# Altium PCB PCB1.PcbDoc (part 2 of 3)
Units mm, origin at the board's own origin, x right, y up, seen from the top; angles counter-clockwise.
Board outline 131.32 x 71.5 mm, 4 copper layers (Top Layer, Layer 1, Layer 2, Bottom Layer), stack 0.603 mm thick; 122 components, 132 nets, 671 pads, 444 vias.
Unrouted connection lines stored in the file: 1.
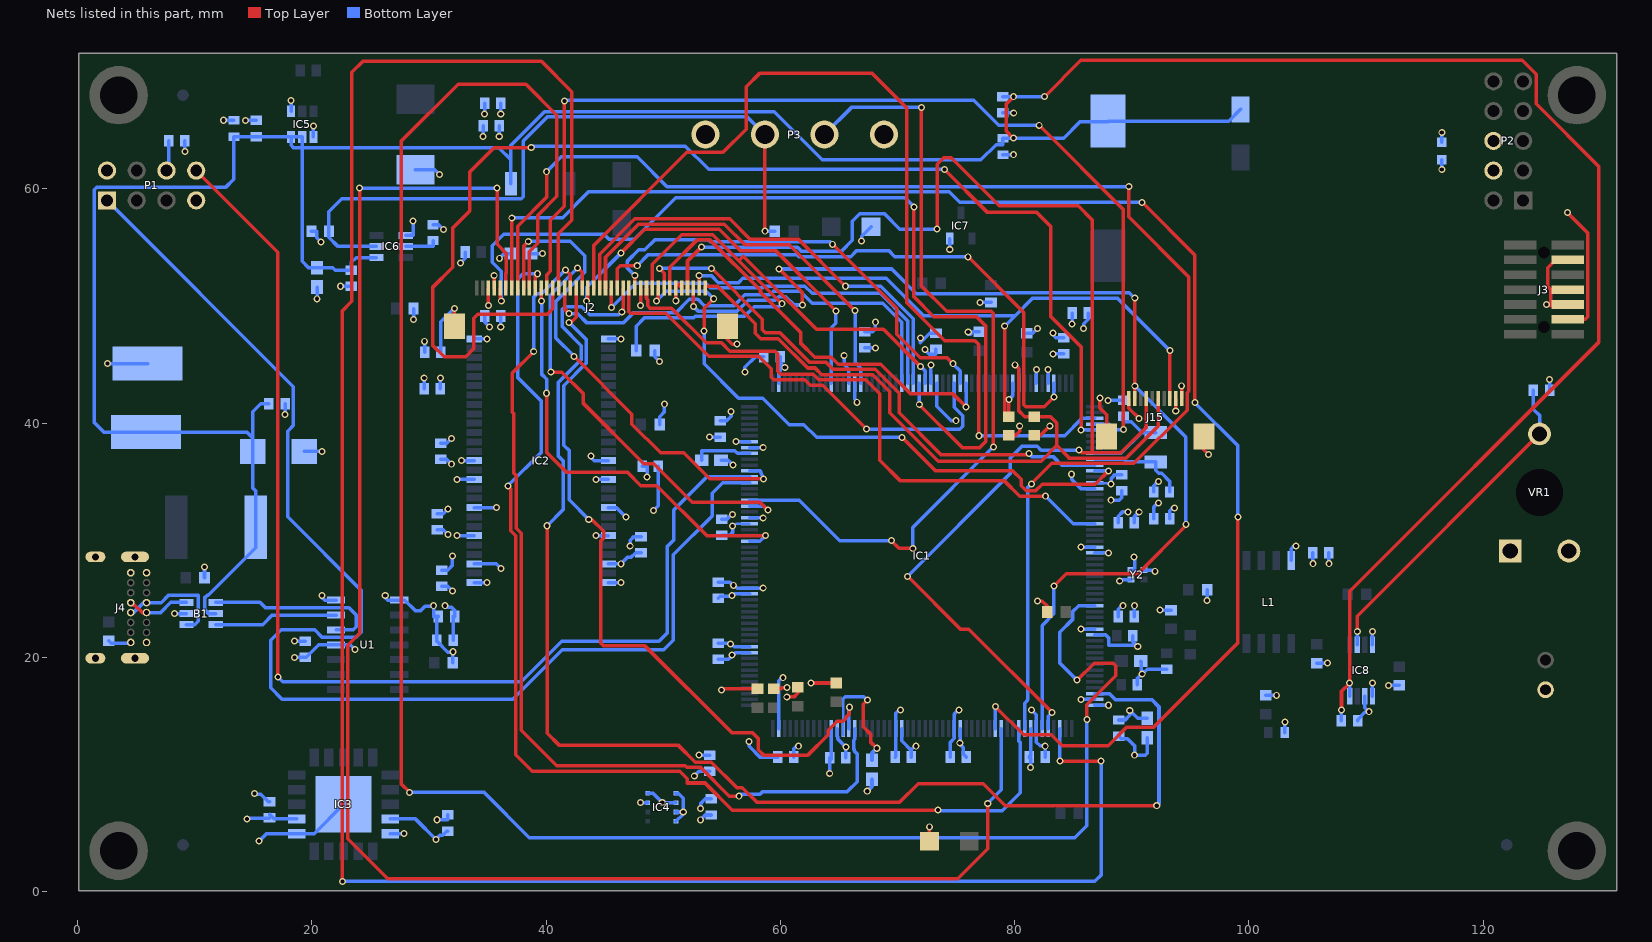
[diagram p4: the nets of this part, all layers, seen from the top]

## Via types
v1: diameter 0.6, hole 0.35, Top Layer to Bottom Layer, 444 vias

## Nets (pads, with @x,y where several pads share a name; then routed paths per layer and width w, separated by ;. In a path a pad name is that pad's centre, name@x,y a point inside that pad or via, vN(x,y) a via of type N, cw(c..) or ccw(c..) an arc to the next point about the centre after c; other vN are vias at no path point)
3V3: C3.1 C4.2 C9.2 C10.2 C11.2 C12.2 C13.2 C14.2 C15.2 C16.2 C17.2 C18.2 C19.2 C20.2 C21.2 C24.2 C25.2 C26.2 C27.2 C28.2 C29.2 C30.2 C33.2 C34.2 C35.1 C36.2 C37.2 C46.2 C47.2 C49.2 C50.2 C51.2 C52.2 C55.2 C56.2 C57.1 C58.2 C59.1 C60.2 C61.2 C62.2 Ferrite.1 IC1.15 IC1.26 IC1.39 IC1.52 IC1.59 IC1.73 IC1.83 IC1.94 IC1.103 IC1.115 IC1.124 IC1.137 IC1.150 IC1.158 IC1.171 IC1.185 IC1.204 IC2.1 IC2.3 IC2.9 IC2.14 IC2.27 IC2.43 IC2.49 IC3.7 IC3.19 IC4.2 IC4.5 IC4.6 IC4.8 IC5.1 IC8.5 J2.4 J3.3 J15.9 L1.8 L3.2 LED1.1 P1.2 P1.6 P2.4 P3.4 R2.1 R3.2 R4.1 R6.1 R9.2 R10.2 R11.1 R12.1 R13.1 R14.1 R17.2 R18.2 R24.1 U1.1 U1.11 VR1.A1 Y2.1 Y2.4 | length 169.9
  Top Layer w0.3: J2.4@35.567,51.529 v1(35.567,52.606) ; v1(54.954,17.221) 55.043,17.31 R9.2@58.039,17.31 ; R11.1@59.436,17.31 60.02,17.31 60.135,17.424 v1(60.554,17.424) ; v1(60.541,16.624) 61.163,16.624 61.468,16.929 R10.2@61.468,17.437 ; v1(62.624,17.818) R12.1@64.77,17.818 ; LED1.1@72.722,4.318 v1(72.722,5.545) ; R18.2@79.502,38.951 80.061,38.951 80.429,39.319 v1(80.429,39.764) ; R17.2@81.661,38.951 82.182,38.951 v1(82.994,39.764) ; v1(81.953,24.803) 82.36,24.803 82.766,24.397 R4.1@82.766,23.876 ; v1(93.75,41.037) J15.9@93.75,42.114 ; v1(127.178,57.988) 128.93,56.236 128.93,49.098 128.694,48.862 J3.3@127.221,48.862
  Bottom Layer w0.3: P1.6@7.366,61.341 P1.6@7.587,61.562 7.786,61.761 C57.1@7.786,64.102 ; v1(14.478,6.223) 14.514,6.259 16.347,6.259 C4.2@16.383,6.295 ; C4.2@16.383,6.602 16.775,6.21 IC3.7@18.7,6.21 ; v1(18.509,20.011) C61.2@19.431,20.011 19.521,20.011 20.592,21.082 U1.11@22.065,21.082 23.267,21.082 v1(23.673,20.676) ; IC5.1@20.127,64.433 v1(20.127,65.36) ; v1(26.263,25.298) 26.263,25.121 26.492,24.892 U1.1@27.465,24.892 27.94,24.892 28.829,24.003 29.304,24.003 29.661,24.36 30.342,24.36 v1(30.4,24.417) 30.4,23.495 C62.2@30.679,23.495 ; IC3.19@26.7,6.21 28.842,6.21 v1(30.607,4.445) 30.607,4.5 30.933,4.826 31.156,4.826 31.5,5.17 C37.2@31.59,5.17 ; L3.2@28.829,61.643 30.475,61.643 v1(30.881,61.237) ; C55.2@29.591,42.926 v1(29.591,43.848) ; C30.2@29.63,46.068 v1(29.63,46.99) ; C25.2@30.701,32.28 31.217,32.28 v1(31.623,32.686) ; C62.2@30.806,23.495 C62.2@30.679,23.495 ; C27.2@30.988,36.902 31.504,36.902 v1(31.91,36.496) ; C28.2@31.082,27.454 31.598,27.454 32.004,27.86 v1(32.004,28.673) ; R24.1@32.042,19.558 v1(32.042,20.485) 32.004,20.447 31.605,20.447 30.679,21.373 C60.2@30.679,21.463 C62.2@30.679,23.495 ; v1(32.788,36.797) IC2.14@33.863,36.797 ; IC2.1@33.863,26.397 v1(34.937,26.397) ; IC2.3@33.863,27.997 35.75,27.997 v1(36.157,27.591) ; IC2.9@33.863,32.797 v1(35.75,32.797) ; IC2.27@33.863,47.197 v1(34.937,47.197) ; v1(34.616,64.483) C47.2@34.616,65.405 ; v1(34.743,66.388) C46.2@34.743,67.31 ; v1(36.013,54.077) 36.419,54.483 C35.1@37.019,54.483 ; v1(36.123,48.227) C34.2@36.123,49.149 ; v1(44.244,30.397) IC2.49@45.319,30.397 ; v1(44.244,35.197) IC2.43@45.319,35.197 ; v1(47.178,29.511) 47.178,29.997 47.505,30.324 C29.2@48.1,30.324 ; v1(48.051,7.606) IC4.2@48.678,7.606 ; C26.2@48.205,36.322 48.611,36.322 v1(48.611,35.4) ; IC4.5@51.078,6.006 51.648,6.576 51.648,6.749 v1(51.705,6.806) ; IC4.6@51.078,6.806 v1(51.705,6.806) ; IC4.8@51.078,8.406 51.128,8.356 51.334,8.356 51.705,7.985 v1(51.705,6.806) ; v1(53.053,11.667) C33.2@53.975,11.667 ; v1(53.18,7.116) 53.18,7.523 53.586,7.929 C36.2@54.102,7.929 ; C49.2@54.704,21.231 54.741,21.194 55.687,21.194 v1(55.724,21.156) 55.806,21.156 56.043,20.919 IC1.115@57.365,20.919 ; C20.2@54.704,25.058 54.862,25.216 55.823,25.216 v1(55.88,25.273) 55.961,25.273 56.107,25.419 IC1.124@57.365,25.419 ; C18.2@54.864,40.187 55.38,40.187 55.786,40.593 v1(55.786,41) ; C19.2@54.991,31.805 55.441,31.805 55.847,32.211 v1(55.913,32.211) ; v1(56.2,38.419) IC1.150@57.365,38.419 ; v1(57.324,12.828) 57.324,12.422 58.246,11.5 C50.2@59.762,11.5 ; IC1.137@57.365,31.919 v1(58.53,31.919) ; IC1.103@59.853,13.931 59.853,18.009 60.114,18.269 v1(60.216,18.269) ; IC1.158@59.853,43.407 59.853,44.374 59.966,44.487 59.966,45.171 ; C16.2@59.966,45.687 59.966,45.171 ; v1(60.372,44.765) 59.966,45.171 ; v1(64.207,10.102) C51.2@64.207,11.43 ; C51.2@64.353,11.303 IC1.94@64.353,13.931 ; IC1.171@66.353,43.407 66.353,42.059 66.548,41.864 v1(66.548,41.783) ; C15.2@67.183,46.427 v1(68.105,46.427) ; C52.2@69.795,11.5 69.853,11.558 IC1.83@69.853,13.931 69.853,15.251 70.104,15.502 v1(70.259,15.502) ; v1(72.357,46.3) 72.357,46.253 72.717,45.894 73.279,45.894 C14.2@73.279,46.3 ; IC1.185@73.353,43.407 73.353,41.43 74.572,40.21 v1(74.979,40.21) ; C58.2@74.494,11.5 74.494,12.744 74.853,13.103 IC1.73@74.853,13.931 74.853,15.171 75.184,15.502 v1(75.259,15.502) ; R2.1@81.026,47.663 81.547,47.663 v1(81.953,48.069) ; v1(81.447,15.502) 81.853,15.096 IC1.59@81.853,13.931 81.853,12.762 82.169,12.446 82.581,12.446 v1(82.605,12.422) C17.2@82.605,11.5 ; IC1.204@82.853,43.407 v1(82.853,44.572) ; v1(83.279,45.919) C13.2@84.201,45.919 ; v1(84.864,35.638) 84.864,35.192 85.637,34.419 IC1.15@86.841,34.419 ; v1(85.676,22.419) IC1.39@86.841,22.419 ; v1(85.882,48.075) 85.882,48.481 86.288,48.887 C56.2@86.288,49.403 ; IC1.52@86.841,15.919 v1(88.006,15.919) ; IC1.26@86.841,28.919 v1(88.006,28.919) ; v1(88.232,33.422) 88.921,33.422 89.154,33.655 C11.2@89.154,34.235 ; C10.2@88.845,23.495 88.845,24.105 89.157,24.417 v1(89.251,24.417) ; C24.2@88.845,31.496 88.845,32.058 89.205,32.418 v1(89.658,32.418) ; C9.2@88.9,13.28 89.11,13.07 89.626,13.07 90.228,12.467 v1(90.228,11.654) 91.137,11.654 91.313,11.83 C3.1@91.313,13.143 ; v1(88.966,26.543) 89.074,26.651 Y2.4@89.92,26.651 ; Y2.1@89.92,27.451 90.264,27.451 90.264,28.495 v1(90.185,28.575) ; C12.2@91.86,31.844 91.86,32.842 92.19,33.172 v1(92.266,33.172) ; v1(92.418,24.041) Ferrite.1@93.345,24.041 ; v1(96.431,24.854) R3.2@96.431,25.781 ; R6.1@101.44,16.769 v1(102.367,16.769) ; L1.8@103.599,28.282 103.599,29.273 103.835,29.509 v1(104.005,29.509) ; R13.1@105.791,19.52 v1(106.718,19.52) ; v1(106.829,28.001) C21.2@106.829,28.923 ; IC8.5@110.543,16.69 v1(110.543,17.817) ; v1(111.911,17.615) R14.1@112.838,17.615 ; v1(116.459,61.669) C59.1@116.459,62.496
+5: +5.1 B1.5 C32.1 C39.2 C42.2 C44.2 C45.2 C48.2 C53.2 C54.2 D1.1 D5.1 F1.2 IC5.2 IC5.3 IC6.1 IC8.8 L2.1 LS1.1 | length 304.9
  Top Layer w0.3: v1(79.891,64.337) 79.299,64.929 79.299,67.259 v1(79.908,67.869) ; v1(82.554,67.873) 85.649,70.968 123.342,70.968 124.511,69.799 124.511,67.259 129.845,61.925 129.845,46.888 108.593,25.637 v1(108.593,17.805) 107.899,17.112 v1(107.899,15.519)
  Bottom Layer w0.3: B1.5@11.791,23.749 11.176,23.749 10.871,24.054 10.871,25.121 11.074,25.324 11.157,25.324 15.196,29.362 F1.2@15.196,31.115 15.196,34.214 14.945,34.465 D1.1@14.945,37.592 14.945,38.725 ; C42.2@16.328,41.656 15.631,41.656 14.945,40.97 14.945,38.725 ; IC6.1@25.514,54.135 23.774,54.135 23.368,53.729 C54.2@23.368,53.069 22.002,53.069 21.793,53.278 C32.1@20.447,53.278 19.71,53.278 19.177,53.811 19.177,63.525 ; L2.1@36.997,60.452 36.997,62.484 ; C45.2@78.994,67.873 v1@79.904,67.873 ; v1(79.908,67.869) v1@79.904,67.873 ; v1(82.554,67.873) v1@79.904,67.873 ; D5.1@99.281,66.787 98.282,65.788 LS1.1@87.978,65.788 87.978,65.735 85.574,65.735 84.176,64.337 v1(79.891,64.337) C44.2@78.994,64.337 78.994,63.779 78.41,63.779 77.114,62.484 63.576,62.484 59.467,66.593 39.861,66.593 36.997,63.729 36.997,62.484 ; C39.2@107.895,14.605 107.895,15.515 v1(107.899,15.519) ; IC8.8@108.593,16.69 v1(108.593,17.805) ; 14.945,38.725 14.427,39.243 +5.1@5.842,39.243 2.235,39.243 1.422,40.056 1.422,59.919 1.626,60.122 12.624,60.122 13.335,60.833 C53.2@13.335,64.441 14.275,64.441 14.295,64.461 C48.2@15.24,64.461 16.713,64.461 16.741,64.433 IC5.3@18.227,64.433 ; IC5.3@18.227,64.433 18.227,63.729 18.43,63.525 19.177,63.525 ; IC5.3@18.227,64.433 IC5.2@19.177,64.433 19.177,63.525 ; 19.177,63.525 35.956,63.525 36.997,62.484
D+: B1.1 J4.A6 J4.B6 | length 9.7
  Bottom Layer w0.3: J4.B6@4.534,23.832 4.775,23.832 5.625,24.682 J4.A6@5.884,24.682 7.137,24.682 7.754,25.299 10.287,25.299 10.287,23.089 9.997,22.799 B1.1@9.291,22.799
D-: B1.3 J4.A7 J4.B7 | length 5.5
  Top Layer w0.3: J4.B7@4.534,24.682 4.756,24.46 4.877,24.46 5.505,23.832 J4.A7@5.884,23.832
  Bottom Layer w0.3: J4.A7@5.884,23.832 7.087,23.832 7.954,24.699 B1.3@9.291,24.699
ESP_RX: IC1.143 P1.1 | length 113.2
  Bottom Layer w0.3: P1.1@2.507,59.022 18.415,43.114 18.415,39.802 17.932,39.319 17.932,32.004 24.232,25.705 24.232,22.2 23.774,21.742 20.853,21.742 20.244,22.352 17.374,22.352 16.485,21.463 16.485,17.399 17.45,16.434 37.16,16.434 41.377,20.65 50.038,20.65 50.851,21.463 50.851,28.753 54.178,32.08 54.178,34.03 55.067,34.919 IC1.143@57.365,34.919
ESP_TX: IC1.144 P1.8 | length 99.6
  Top Layer w0.3: P1.8@10.127,61.562 17.094,54.595 v1(17.094,18.339)
  Bottom Layer w0.3: v1(17.094,18.339) 17.501,17.932 37.871,17.932 41.326,21.387 49.632,21.387 50.317,22.073 50.317,29.447 50.896,30.025 50.896,32.582 53.732,35.419 IC1.144@57.365,35.419
GND: B1.2 C1.1 C2.1 C3.2 C4.1 C5.2 C6.2 C7.2 C8.1 C9.1 C10.1 C11.1 C12.1 C13.1 C14.1 C15.1 C16.1 C17.1 C18.1 C19.1 C20.1 C21.1 C22.1 C23.1 C24.1 C25.1 C26.1 C27.1 C28.1 C29.1 C30.1 C31.1 C32.2 C33.1 C34.1 C35.2 C36.1 C37.1 C38.1 C39.1 C40.1 C41.1 C42.1 C44.1 C45.1 C46.1 C47.1 C48.1 C49.1 C50.1 C51.1 C52.1 C53.1 C54.1 C55.1 C56.1 C57.2 C58.1 C59.2 C60.1 C61.1 C62.1 D1.2 GND.1 IC1.14 IC1.25 IC1.40 IC1.51 IC1.60 IC1.72 IC1.82 IC1.93 IC1.114 IC1.125 IC1.136 IC1.149 IC1.170 IC1.184 IC1.202 IC2.6 IC2.12 IC2.28 IC2.41 IC2.46 IC2.52 IC2.54 IC3.6 IC3.20 IC3.21 IC4.1 IC4.7 IC5.4 IC6.4 IC7.2 IC8.4 IC8.6 J2.3 J2.29 J2.35 J2.36 J2.41 J2.42 J3.5 J3.7 J3.11 J4.A1 J4.A12 J4.B1 J4.B12 J4.S1 J4.S2 J4.S3 J4.S4 J15.1 J15.10 J15.11 J15.12 LED2.2 P1.7 P2.6 P3.1 Q1.1 R1.2 R7.1 R8.1 R16.2 R21.1 R22.1 R23.1 R26.1 U1.14 VR1.E1 Y2.2 | length 183.7
  Top Layer w0.3: J2.41@32.167,48.279 v1(32.167,49.806) ; v1(35.067,50.046) J2.3@35.067,51.529 ; v1(48.067,50.046) J2.29@48.067,51.529 ; v1(51.067,50.452) 51.067,51.864 51.317,51.864 ; J2.35@51.097,51.864 51.567,51.864 J2.36@51.567,51.529 51.317,51.779 ; J2.42@55.467,48.279 55.467,47.158 55.873,46.752 v1(56.28,46.752) ; v1(87.274,42.142) 87.274,41.297 87.85,40.721 J15.11@87.85,38.864 ; J15.1@89.75,42.114 89.75,41.28 v1(90.627,40.403) ; J15.10@94.25,42.114 v1(94.25,43.191) ; J15.12@96.15,38.864 96.15,37.743 v1(96.556,37.337) ; v1(125.399,50.132) 125.456,50.075 125.668,50.075 125.705,50.038 125.781,50.038 125.781,51.402 ; 125.781,50.132 J3.5@127.221,50.132 ; J3.7@127.221,51.402 125.781,51.402 ; J3.11@127.221,53.942 126.187,53.942 125.501,53.256 125.501,51.681 125.781,51.402
  Bottom Layer w0.2: v1(55.913,31.238) 55.988,31.313 56.096,31.313 56.202,31.419 IC1.136@57.365,31.419 ; IC1.14@86.841,34.919 86.891,34.869 88.165,34.869 v1(88.232,34.802)
  Bottom Layer w0.3: v1(2.542,45.085) GND.1@5.969,45.085 ; R22.1@2.667,21.425 2.877,21.215 4.467,21.215 J4.B1@4.534,21.282 ; v1(8.264,23.749) B1.2@9.291,23.749 ; v1(9.166,63.18) C57.2@9.166,64.102 ; R23.1@10.833,26.797 v1(10.833,27.724) ; v1(12.438,65.861) C53.1@13.335,65.861 ; v1(14.318,65.841) C48.1@15.24,65.841 ; v1(15.113,8.382) 15.17,8.325 15.643,8.325 16.293,7.675 C4.1@16.383,7.675 ; v1(15.494,4.318) 15.494,4.329 16.125,4.96 IC3.6@18.7,4.96 20.2,4.96 IC3.21@22.7,7.46 ; v1(17.708,40.734) C42.1@17.708,41.656 ; IC5.4@18.227,66.631 v1(18.227,67.558) ; v1(18.509,21.391) C61.1@19.431,21.391 ; D1.2@19.345,37.592 v1(20.872,37.592) ; R16.2@19.951,56.388 20.401,56.388 20.401,55.824 v1(20.764,55.461) ; v1(20.447,50.618) C32.2@20.447,51.624 ; v1(20.863,25.298) 20.863,25.121 21.092,24.892 U1.14@22.065,24.892 ; v1(22.446,51.689) C54.1@23.368,51.689 ; IC3.20@26.7,4.96 v1(27.877,4.96) ; IC6.4@28.014,56.035 28.635,56.035 v1(28.635,57.254) ; v1(28.69,48.857) R8.1@28.69,49.784 ; C31.1@30.353,56.931 30.844,56.931 v1(31.25,56.525) ; v1(30.668,6.144) 31.59,6.144 C37.1@31.59,6.55 ; C25.1@30.701,30.9 31.217,30.9 v1(31.623,30.494) ; C55.1@30.971,42.926 v1(30.971,43.848) ; C27.1@30.988,38.282 31.504,38.282 v1(31.91,38.688) ; C30.1@31.01,46.068 31.01,48.649 v1(32.167,49.806) ; C28.1@31.082,26.074 31.598,26.074 v1(32.004,25.668) ; v1(31.373,24.417) 31.485,24.305 31.892,24.305 32.186,24.011 C62.1@32.186,23.495 ; C60.1@32.059,21.463 C62.1@32.059,23.495 ; v1(32.382,30.397) IC2.6@33.863,30.397 ; v1(32.382,35.197) IC2.12@33.863,35.197 ; v1(32.686,53.688) 33.092,54.094 C38.1@33.092,54.61 ; C34.1@34.743,49.149 34.743,48.633 v1(35.149,48.227) ; v1(35.996,64.483) C47.1@35.996,65.405 ; v1(36.123,66.388) C46.1@36.123,67.31 ; C35.2@38.673,54.483 v1(39.679,54.483) ; v1(43.838,37.203) 43.838,37.053 44.094,36.797 IC2.41@45.319,36.797 ; IC2.54@45.319,26.397 v1(46.394,26.397) ; IC2.52@45.319,27.997 v1(46.394,27.997) 46.934,28.538 47.23,28.538 47.637,28.944 C29.1@48.1,28.944 ; IC2.46@45.319,32.797 45.987,32.797 v1(46.8,31.984) ; IC2.28@45.319,47.197 v1(46.394,47.197) ; IC4.1@48.678,8.406 49.125,8.406 v1(49.911,7.62) 49.918,7.613 51.071,7.613 IC4.7@51.078,7.606 ; v1(49.179,32.555) 49.585,32.962 C26.1@49.585,36.322 ; R7.1@49.281,46.195 49.281,45.674 v1(49.687,45.268) ; R26.1@49.695,39.878 49.695,40.564 50.101,40.97 v1(50.101,41.618) ; v1(52.647,9.881) 53.053,10.287 C33.1@53.975,10.287 ; v1(53.18,6.143) 53.586,6.549 C36.1@54.102,6.549 ; v1(53.942,38.807) C18.1@54.864,38.807 ; C49.1@54.704,19.851 55.566,19.851 55.88,20.165 v1(55.88,20.193) 55.961,20.193 56.187,20.419 IC1.114@57.365,20.419 ; C20.1@54.704,26.438 55.65,26.438 55.926,26.162 v1(56.007,26.162) 56.078,26.162 56.321,25.919 IC1.125@57.365,25.919 v1(58.53,25.919) ; C6.2@54.929,36.83 55.529,36.83 v1(55.935,36.424) ; C19.1@54.991,30.425 55.677,30.425 55.913,30.661 v1(55.913,31.238) ; v1(56.96,44.359) 56.96,44.765 57.882,45.687 C16.1@58.586,45.687 ; IC1.149@57.365,37.919 v1(58.53,37.919) ; C50.1@61.142,11.5 61.142,12.198 61.366,12.422 v1(61.548,12.422) ; IC1.93@64.853,13.931 64.853,13.252 64.897,13.208 64.897,13.042 v1(65.587,12.352) C51.1@65.587,11.43 ; v1(65.447,45.791) 65.447,44.978 65.853,44.572 IC1.170@65.853,43.407 ; v1(66.927,55.542) 66.927,55.956 LED2.2@67.74,56.769 ; C15.1@67.183,47.807 67.869,47.807 68.105,48.043 v1(68.105,48.62) ; v1(67.412,8.581) 67.818,8.987 C7.2@67.818,9.587 ; IC1.82@70.353,13.931 70.353,12.878 71.175,12.056 ; C52.1@71.175,11.5 71.175,12.056 ; v1(71.581,12.422) 71.481,12.422 71.175,12.116 71.175,12.056 ; v1(71.951,47.274) 71.951,46.867 72.763,47.68 C14.1@73.279,47.68 ; IC1.184@72.853,43.407 v1(72.853,44.978) ; v1(74.455,54.811) IC7.2@74.455,55.763 ; v1(75.311,12.7) 75.311,12.619 75.619,12.311 75.619,11.755 C58.1@75.874,11.5 ; v1@75.353,12.766 IC1.72@75.353,13.931 ; v1(76.035,47.79) 76.035,47.603 76.254,47.603 76.441,47.79 R1.2@76.962,47.79 ; v1(77.051,50.304) R21.1@77.978,50.304 ; C44.1@78.994,62.917 v1(79.891,62.917) ; C45.1@78.994,66.493 v1(79.916,66.493) ; v1(81.35,10.598) 81.35,11.375 C17.1@81.225,11.5 81.353,11.628 IC1.60@81.353,13.931 ; IC1.202@81.853,43.407 v1(81.853,44.572) ; v1(83.279,47.705) 83.279,47.535 83.515,47.299 C13.1@84.201,47.299 ; v1(84.908,48.481) C56.1@84.908,49.403 ; v1(85.676,16.419) IC1.51@86.841,16.419 ; v1(85.676,29.419) IC1.25@86.841,29.419 ; IC1.40@86.841,21.919 87.782,21.919 88.011,21.69 88.011,21.031 v1@90.395,21.031 ; v1(87.978,41.945) C22.1@89.281,41.945 ; v1(88.232,34.802) 88.232,35.281 88.566,35.615 C11.1@89.154,35.615 ; C9.1@88.9,14.66 89.416,14.66 89.822,15.066 v1(89.822,15.473) 90.5,14.795 90.5,14.797 C3.2@91.313,14.797 ; C1.1@90.098,21.844 90.098,21.328 v1@90.395,21.031 ; C10.1@90.225,23.495 v1(90.225,24.417) ; C24.1@90.225,31.496 90.225,32.029 90.614,32.418 v1(90.631,32.418) ; C8.1@90.479,17.653 90.479,18.224 90.83,18.575 v1(90.885,18.575) 91.305,18.995 C2.1@92.964,18.995 ; v1@90.5,20.93 90.399,21.031 v1@90.395,21.031 ; v1(90.504,20.922) v1@90.395,21.031 ; C5.2@90.743,19.685 90.823,19.605 90.823,18.905 v1@90.966,18.762 ; Y2.2@91.02,27.451 91.879,27.451 v1(91.974,27.356) ; C23.1@91.88,34.13 91.88,34.671 92.236,35.027 v1(92.286,35.027) ; C12.1@93.24,31.844 93.24,32.534 93.472,32.766 v1(93.646,32.766) ; C41.1@103.072,13.589 v1(103.072,14.486) ; v1(105.449,28.001) C21.1@105.449,28.923 ; C39.1@109.275,14.605 109.275,14.695 109.89,15.31 110.179,15.31 v1(110.236,15.367) 109.893,15.71 IC8.6@109.893,16.69 ; IC8.4@110.543,21.09 v1(110.543,22.217) ; C59.2@116.459,63.996 v1(116.459,64.823) ; C40.1@125.658,42.799 v1(125.658,43.721)
LCD_B0: IC1.3 J2.21 | length 82.4
  Top Layer w0.3: J2.21@44.067,51.529 44.067,55.169 52.017,63.119 55.093,63.119 57.074,65.1 57.074,68.707 58.258,69.891 67.802,69.891 70.79,66.904 70.79,50.292 74.041,47.041 76.606,47.041 76.937,46.711 v1(76.937,38.926)
  Bottom Layer w0.3: v1(76.937,38.926) 84.257,38.926 85.75,40.419 IC1.3@86.841,40.419
LCD_B1: IC1.181 J2.22 | length 40
  Top Layer w0.3: J2.22@44.567,51.529 44.567,54.435 47.574,57.442 55.664,57.442 57.42,55.685 61.553,55.685 v1(65.549,51.689)
  Bottom Layer w0.3: v1(65.549,51.689) 68.58,51.689 71.351,48.918 71.351,46.27 71.353,46.267 IC1.181@71.353,43.407
LCD_B2: IC1.172 J2.23 | length 34.6
  Top Layer w0.3: J2.23@45.067,51.529 45.067,54.176 47.883,56.992 55.214,56.992 56.97,55.235 60.741,55.235 v1(66.37,49.606)
  Bottom Layer w0.3: v1(66.37,49.606) 66.37,45.187 66.853,44.704 IC1.172@66.853,43.407
LCD_B3: IC1.180 J2.24 | length 34.6
  Top Layer w0.3: v1(45.567,49.86) J2.24@45.567,51.529
  Bottom Layer w0.3: v1(45.567,49.86) 47.661,51.954 53.616,51.954 54.021,51.549 58.476,51.549 58.626,51.699 62.089,51.699 62.708,51.079 68.511,51.079 70.853,48.738 IC1.180@70.853,43.407
LCD_B4: IC1.205 J2.25 | length 51.4
  Top Layer w0.3: J2.25@46.067,51.529 46.067,53.179 46.33,53.442 v1(47.777,53.442) ; v1(76.022,54.204) 80.779,49.447 80.779,41.578 80.955,41.402 82.525,41.402 v1(83.363,42.24)
  Bottom Layer w0.3: v1(47.777,53.442) 48.73,54.394 61.366,54.394 61.55,54.211 65.996,54.211 66.523,54.737 69.24,54.737 69.774,54.204 v1(76.022,54.204) ; IC1.205@83.353,43.407 83.353,42.25 v1(83.363,42.24)
LCD_B5: IC1.50 J2.26 | length 116.5
  Top Layer w0.3: v1(40.081,31.242) 40.081,13.538 41.097,12.522 51.259,12.522 52.714,11.067 54.096,11.067 56.291,8.872 56.755,8.872 58.006,7.62 70.155,7.62 71.755,9.22 77.307,9.22 79.186,7.341 v1(92.126,7.341) ; v1(46.457,49.505) 46.567,49.615 J2.26@46.567,51.529
  Bottom Layer w0.3: v1(40.081,31.242) 41.478,32.639 41.478,36.754 41.053,37.179 41.053,43.491 42.994,45.432 42.994,46.615 41.361,48.248 41.361,49.708 41.605,49.952 43.028,49.952 43.729,49.251 46.203,49.251 v1(46.457,49.505) ; IC1.50@86.841,16.919 88.062,16.919 88.573,16.408 91.685,16.408 92.319,15.773 92.319,7.534 v1(92.126,7.341)
LCD_B6: IC1.188 J2.27 | length 39.2
  Top Layer w0.3: J2.27@47.067,51.529 47.067,49.523 47.221,49.369 50.199,49.369 53.866,45.702 58.159,45.702 59.221,44.639 59.221,43.915 59.422,43.715 62.07,43.715 62.542,43.242 63.61,43.242 v1(67.365,39.487)
  Bottom Layer w0.3: v1(67.365,39.487) 75.315,39.487 75.579,39.751 75.579,40.619 74.853,41.345 IC1.188@74.853,43.407
LCD_B7: IC1.189 J2.28 | length 38.7
  Top Layer w0.3: J2.28@47.567,51.529 v1(47.567,52.603) ; v1(64.458,55.27) 69.925,49.804 69.925,47.602 71.949,45.578 74.225,45.578 v1(74.727,45.076)
  Bottom Layer w0.3: v1(47.567,52.603) 46.939,53.231 46.939,53.841 47.897,54.799 48.424,54.799 49.267,55.642 53.864,55.642 54.028,55.478 64.251,55.478 v1(64.458,55.27) ; v1(74.727,45.076) 75.353,44.45 IC1.189@75.353,43.407
LCD_BL_CTRL: IC1.140 P3.2 | length 70.1
  Top Layer w0.3: v1(69.467,29.972) 70.127,29.312 v1(71.298,29.312) ; v1(72.034,66.954) 72.034,51.714 74.193,49.555 78.003,49.555 78.181,49.378 v1(78.181,37.973)
  Bottom Layer w0.3: IC1.140@57.365,33.419 61.62,33.419 65.067,29.972 v1(69.467,29.972) ; P3.2@63.754,64.643 66.065,66.954 v1(72.034,66.954) ; v1(71.298,29.312) 71.298,31.09 v1(78.181,37.973)
LCD_BL_CTRL_TP: IC6.2 P3.3 R16.1 R19.2 | length 59.7
  Top Layer w0.3: v1(58.674,56.388) P3.3@58.674,64.643
  Bottom Layer w0.3: IC6.2@25.514,55.085 22.233,55.085 21.451,55.867 R16.1@21.451,56.388 21.451,58.048 22.555,59.152 37.867,59.152 38.049,59.334 38.049,64.084 40.108,66.143 57.174,66.143 P3.3@58.674,64.643 ; v1(58.674,56.388) R19.2@59.525,56.388
LCD_DCLK: IC1.21 J2.30 | length 51.6
  Top Layer w0.3: J2.30@48.567,51.529 48.567,50.646 48.667,50.546 48.667,50.014 48.862,49.819 50.698,49.819 53.654,46.863 54.966,46.863 55.677,46.152 59.537,46.152 59.766,45.923 59.766,44.425 60.026,44.165 62.803,44.165 63.276,43.693 67.293,43.693 68.478,42.507 68.478,36.837 70.213,35.103 79.087,35.103 80.427,33.763 v1(82.645,33.763)
  Bottom Layer w0.3: v1(82.645,33.763) 84.989,31.419 IC1.21@86.841,31.419
LCD_DE: IC1.190 J2.34 | length 36.6
  Top Layer w0.3: J2.34@50.567,51.529 50.567,52.006 50.561,52.012 50.561,53.327 52.876,55.642 53.99,55.642 58.298,51.333 58.298,51.176 61.715,47.759 61.715,46.845 62.918,45.642 64.343,45.642 64.942,45.043 68.572,45.043 71.12,42.494 74.735,42.494 v1(75.853,41.377)
  Bottom Layer w0.3: v1(75.853,41.377) IC1.190@75.853,43.407
LCD_DISP: IC1.183 J2.31 R7.2 | length 53.1
  Top Layer w0.3: J2.31@49.067,51.529 49.067,52.607 49.061,52.613 49.061,53.569 51.584,56.092 54.233,56.092 56.453,53.872 ; v1(60.126,50.199) 56.453,53.872 ; v1(71.963,44.84) 68.797,48.006 63.082,48.006 56.835,54.253 56.453,53.872
  Bottom Layer w0.3: R7.2@47.681,46.195 47.681,48.285 48.391,48.996 52.609,48.996 52.736,49.122 56.934,49.122 57.755,49.943 59.87,49.943 v1(60.126,50.199) ; v1(71.963,44.84) 72.353,44.45 IC1.183@72.353,43.407
LCD_G0: IC1.4 J2.13 | length 89.6
  Top Layer w0.3: J2.13@40.067,51.529 40.067,52.68 40.361,52.973 40.361,57.328 41.554,58.522 41.554,67.462 v1(41.58,67.488) ; v1(82.093,65.43) 89.281,58.242 v1(89.281,39.446)
  Bottom Layer w0.3: v1(41.58,67.488) 41.656,67.564 76.505,67.564 78.638,65.43 v1(82.093,65.43) ; IC1.4@86.841,39.919 88.087,39.919 88.56,39.446 v1(89.281,39.446)
LCD_G1: IC1.5 J2.14 | length 104.7
  Top Layer w0.3: v1(38.728,63.518) 35.553,63.518 33.477,61.443 33.477,58.115 32.029,56.667 32.029,53.315 30.302,51.587 30.302,46.66 31.293,45.669 33.122,45.669 33.826,46.373 33.826,48.965 34.162,49.301 40.11,49.301 40.567,49.759 J2.14@40.567,51.529 ; v1(73.99,61.671) 77.673,57.988 81.89,57.988 83.058,56.82 83.058,49.124 85.674,46.507 v1(85.674,39.421)
  Bottom Layer w0.3: v1(38.728,63.518) 38.864,63.654 51.89,63.654 53.873,61.671 v1(73.99,61.671) ; v1(85.674,39.421) 85.676,39.419 IC1.5@86.841,39.419
LCD_G2: IC1.55 J2.15 | length 187.9
  Top Layer w0.3: v1(22.606,0.889) 22.606,49.581 23.419,50.394 23.419,69.952 24.359,70.891 39.599,70.891 42.189,68.301 42.189,57.328 41.046,56.185 41.046,52.218 41.067,52.197 J2.15@41.067,51.529 ; v1(83.853,11.151) v1(87.376,11.151)
  Bottom Layer w0.3: v1(22.606,0.889) 86.843,0.889 87.376,1.422 v1(87.376,11.151) ; v1(83.853,11.151) IC1.55@83.853,13.931
LCD_G3: IC1.179 J2.16 | length 38.9
  Top Layer w0.3: J2.16@41.567,51.529 41.567,49.746 v1(41.961,49.352)
  Bottom Layer w0.3: v1(41.961,49.352) 42.688,49.352 43.486,48.555 46.582,48.555 47.473,49.446 51.097,49.446 52.222,50.571 52.959,50.571 53.508,50.022 56.036,50.022 56.964,50.95 59.076,50.95 59.375,51.249 61.708,51.249 62.724,50.233 68.722,50.233 70.353,48.601 IC1.179@70.353,43.407
LCD_G4: IC1.90 J2.17 | length 79.7
  Top Layer w0.3: v1(38.938,46.102) 37.115,44.278 37.115,40.928 37.25,40.793 37.25,35.715 37.436,35.53 37.436,31.043 37.871,30.607 37.871,13.772 40.9,10.744 51.876,10.744 52.003,10.617 53.18,10.617 55.643,8.153 v1(56.464,8.153) ; v1(41.656,53.086) 42.067,52.675 J2.17@42.067,51.529
  Bottom Layer w0.3: v1(38.938,46.102) 38.938,50.775 39.218,51.054 39.624,51.054 v1(41.656,53.086) ; v1(56.464,8.153) 56.626,8.315 58.251,8.315 58.487,8.551 65.701,8.551 66.548,9.398 66.548,11.76 66.294,12.014 66.294,12.141 66.243,12.192 66.243,12.903 66.353,13.013 IC1.90@66.353,13.931
LCD_G5: IC1.91 J2.18 | length 63.6
  Top Layer w0.3: v1(41.961,48.59) 42.104,48.59 42.567,49.054 J2.18@42.567,51.529 ; v1(43.637,31.775) 43.891,31.775 44.907,30.759 44.907,30.201 44.679,29.972 44.679,21.209 44.907,20.98 48.438,20.98 55.829,13.589 57.607,13.589 58.115,13.081 58.115,12.116 58.598,11.633 62.306,11.633 64.081,13.408 64.081,13.789 64.841,14.549 65.349,14.549 65.558,14.758 65.558,14.848 65.856,15.145 65.856,15.691 v1(65.913,15.748)
  Bottom Layer w0.3: v1(41.961,48.59) 43.444,47.107 43.444,45.145 41.503,43.204 41.503,38.126 41.961,37.668 41.961,33.452 v1(43.637,31.775) ; IC1.91@65.853,13.931 65.853,15.607 65.913,15.667 v1(65.913,15.748)
LCD_G6: IC1.139 J2.19 | length 37.4
  Top Layer w0.3: v1(40.395,44.357) 41.342,44.357 43.186,42.513 43.186,41.675 48.34,36.522 49.2,36.522 52.461,33.261 58.255,33.261 v1(58.928,32.588) ; v1(42.691,53.257) 43.067,52.881 J2.19@43.067,51.529
  Bottom Layer w0.3: v1(40.395,44.357) 40.361,44.391 40.361,50.928 v1(42.691,53.257) ; IC1.139@57.365,32.919 58.597,32.919 v1(58.928,32.588)
LCD_G7: IC1.167 J2.20 | length 34.8
  Top Layer w0.3: v1(43.459,50.444) 43.567,50.552 J2.20@43.567,51.529 ; v1(46.391,54.523) 48.409,56.542 54.764,56.542 56.602,54.703 59.623,54.703 v1(64.735,49.591)
  Bottom Layer w0.3: v1(43.459,50.444) 43.459,51.592 v1(46.391,54.523) ; IC1.167@64.353,43.407 64.353,48.142 64.735,48.524 v1(64.735,49.591)
LCD_HSYNC: IC1.12 J2.32 | length 53.7
  Top Layer w0.3: v1(49.428,50.444) 49.567,50.583 J2.32@49.567,51.529 ; v1(53.492,47.879) 53.492,49.809 v1(54.305,50.622) ; v1(70.383,38.786) 73.25,35.919 79.848,35.919 80.569,35.198 80.569,34.671 81.027,34.213 81.767,34.213 82.336,34.782 86.874,34.782 v1(88.011,35.919)
  Bottom Layer w0.3: v1(49.428,50.444) 50.259,51.275 53.652,51.275 v1(54.305,50.622) ; v1(53.492,47.879) 53.492,45.06 56.422,42.13 58.505,42.13 60.757,39.878 62.003,39.878 63.095,38.786 v1(70.383,38.786) ; IC1.12@86.841,35.919 v1(88.011,35.919)
LCD_INT: IC1.58 J2.38 J15.2 | length 95.5
  Top Layer w0.3: J2.38@52.567,51.529 52.567,49.973 v1(52.578,49.962) ; v1(59.893,53.162) 61.874,51.181 v1(61.874,50.089) ; v1(83.347,26.086) 84.414,27.153 90.526,27.153 94.615,31.242 v1(94.615,31.369) ; J15.2@90.25,42.114 v1(90.25,43.18) v1(90.25,50.673)
  Bottom Layer w0.3: v1(52.578,49.962) 52.968,49.572 56.324,49.572 57.252,50.5 59.538,50.5 59.837,50.799 60.447,50.799 61.157,50.089 v1(61.874,50.089) ; v1(59.893,53.162) 69.494,53.162 71.603,51.054 79.019,51.054 79.096,51.13 89.793,51.13 v1(90.25,50.673) ; IC1.58@82.353,13.931 82.353,22.724 83.347,23.718 v1(83.347,26.086) ; v1(90.25,43.18) 94.615,38.815 v1(94.615,31.369)
LCD_R0: IC1.182 J2.5 | length 78.5
  Top Layer w0.3: J2.5@36.067,51.529 36.067,50.547 v1(36.17,50.444) ; v1(71.399,58.471) 71.399,50.8 73.101,49.098 76.733,49.098 77.546,48.285 77.546,38.456 77.013,37.922 75.511,37.922 v1(71.853,41.58)
  Bottom Layer w0.3: v1(36.17,50.444) 36.17,52.984 35.408,53.746 35.408,55.159 36.373,56.124 44.939,56.124 45.364,55.699 47.524,55.699 51.058,59.233 70.637,59.233 v1(71.399,58.471) ; v1(71.853,41.58) IC1.182@71.853,43.407
LCD_R1: IC1.65 J2.6 | length 144.5
  Top Layer w0.3: v1(24.079,60.071) 24.079,22.073 23.063,21.057 23.063,4.521 26.492,1.092 75.133,1.092 77.699,3.658 v1(77.699,7.544) ; v1(35.814,60.071) 35.814,55.27 36.613,54.471 36.613,52.832 36.567,52.786 J2.6@36.567,51.529
  Bottom Layer w0.3: v1(24.079,60.071) v1(35.814,60.071) ; v1(77.699,7.544) 78.853,8.698 IC1.65@78.853,13.931
LCD_R2: IC1.66 J2.7 | length 129.7
  Top Layer w0.3: J2.7@37.067,51.529 v1(37.067,57.531) ; v1(78.353,15.799) 80.766,13.386 83.118,13.386 84.047,12.457 87.971,12.457 89.574,14.06 91.875,14.06 99.06,21.245 v1(99.06,32.004) ; v1(90.881,58.852) 95.377,54.356 v1(95.377,41.758)
  Bottom Layer w0.3: v1(37.067,57.531) 41.402,57.531 43.612,59.741 74.422,59.741 75.311,58.852 v1(90.881,58.852) ; IC1.66@78.353,13.931 v1(78.353,15.799) ; v1(95.377,41.758) 99.06,38.075 v1(99.06,32.004)
LCD_R3: IC1.61 J2.8 | length 120.5
  Top Layer w0.3: J2.8@37.567,51.529 37.567,56.82 40.03,59.284 v1(40.03,61.468) ; v1(81.422,34.813) 83.173,36.564 90.173,36.564 94.717,41.108 94.717,42.596 94.869,42.748 94.869,52.476 89.738,57.607 v1(89.738,60.198)
  Bottom Layer w0.3: v1(40.03,61.468) 41.3,62.738 47.777,62.738 50.317,60.198 v1(89.738,60.198) ; IC1.61@80.853,13.931 80.853,14.896 80.847,14.902 80.847,16.096 81.12,16.369 81.12,34.511 v1(81.422,34.813)
LCD_R4: IC1.145 J2.9 | length 42.4
  Top Layer w0.3: J2.9@38.067,51.529 38.067,55.118 v1(38.473,55.524) ; v1(42.385,45.703) 47.319,40.768 47.319,39.914 49.77,37.462 51.756,37.462 53.977,35.241 v1(58.563,35.241)
  Bottom Layer w0.3: v1(38.473,55.524) 42.062,55.524 43.307,54.28 43.307,52.883 40.811,50.387 40.811,47.276 v1(42.385,45.703) ; IC1.145@57.365,35.919 58.285,35.919 v1(58.563,35.241)
LCD_R5: IC1.35 J2.10 | length 175.6
  Top Layer w0.3: v1(28.346,8.484) 27.61,9.22 27.61,64.059 32.487,68.936 38.278,68.936 40.919,66.294 40.919,59.36 39.294,57.734 39.294,55.372 38.567,54.645 J2.10@38.567,51.529 ; v1(85.319,18.059) 86.778,19.519 88.392,19.519 88.611,19.3 88.611,18.431 86.157,15.977 v1(86.157,14.707)
  Bottom Layer w0.3: v1(28.346,8.484) 34.696,8.484 38.557,4.623 85.141,4.623 86.157,5.639 v1(86.157,14.707) ; v1(85.319,18.059) 83.855,19.523 83.855,22.156 84.938,23.238 84.938,23.901 85.455,24.419 IC1.35@86.841,24.419
LCD_R6: IC1.62 J2.11 | length 97.5
  Top Layer w0.3: v1(36.728,34.646) 36.986,34.388 36.986,30.807 37.414,30.378 37.414,11.684 38.811,10.287 51.419,10.287 52.047,9.66 52.047,9.281 53.565,9.281 55.886,6.96 v1(73.457,6.96) ; J2.11@39.067,51.529 39.067,52.554 v1(39.268,52.756)
  Bottom Layer w0.3: v1(36.728,34.646) 39.599,37.516 39.599,41.885 37.592,43.891 37.592,52.349 37.998,52.756 v1(39.268,52.756) ; v1(73.457,6.96) 73.496,6.921 78.93,6.921 80.467,8.458 80.467,12.738 80.353,12.852 IC1.62@80.353,13.931
LCD_R7: IC1.133 J2.12 | length 37.4
  Top Layer w0.3: J2.12@39.567,51.529 39.567,50.464 v1(39.604,50.426) ; v1(40.046,42.554) 40.046,37.5 41.732,35.814 46.945,35.814 48.086,34.673 49.452,34.673 53.716,30.408 v1(58.723,30.408)
  Bottom Layer w0.3: v1(39.604,50.426) 39.604,44.197 40.046,43.755 v1(40.046,42.554) ; IC1.133@57.365,29.919 58.233,29.919 v1(58.723,30.408)
LCD_RST: IC1.57 J2.37 J15.4 | length 116.2
  Top Layer w0.3: J2.37@52.067,51.529 52.067,53.845 v1(53.264,55.042) ; v1(70.856,26.924) 75.368,22.413 76.088,22.413 v1(83.185,15.316) ; v1(73.381,56.566) 73.381,62.103 73.939,62.662 74.574,62.662 78.689,58.547 85.42,58.547 86.639,57.328 86.639,37.464 ; v1(85.496,37.694) 85.726,37.464 86.639,37.464 ; J15.4@91.25,42.114 91.25,39.664 89.05,37.464 86.639,37.464
  Bottom Layer w0.3: v1(53.264,55.042) 53.264,55.027 61.457,55.027 61.824,54.661 65.202,54.661 66.142,55.601 66.142,57.226 66.784,57.869 68.885,57.869 70.188,56.566 v1(73.381,56.566) ; v1(70.856,26.924) 79.604,35.671 79.604,37.008 80.622,38.026 81.915,38.026 82.247,37.694 v1(85.496,37.694) ; IC1.57@82.853,13.931 82.853,14.984 v1(83.185,15.316)
LCD_SCL: IC1.198 J2.39 J15.8 R18.1 | length 61.9
  Top Layer w0.3: J2.39@53.067,51.529 v1(53.067,52.603) ; v1(79.146,48.285) 79.146,40.551 R18.1@79.502,40.551 v1(79.502,42.016) ; J15.8@93.25,42.114 v1(93.25,46.203)
  Bottom Layer w0.3: v1(53.067,52.603) 54.09,52.603 54.694,51.999 56.426,51.999 56.785,52.359 69.027,52.359 72.211,49.174 80.035,49.174 ; v1(79.146,48.285) 80.035,49.174 ; v1(79.502,42.016) 79.853,42.367 IC1.198@79.853,43.407 ; v1(93.25,46.203) 88.805,50.648 81.509,50.648 80.035,49.174
LCD_SDA: IC1.199 J2.40 J15.6 R17.1 | length 62.4
  Top Layer w0.3: J2.40@53.567,51.529 53.567,51.705 54.621,51.705 57.852,48.475 57.852,47.676 58.318,47.209 59.828,47.209 62.327,44.71 62.954,44.71 63.521,44.143 67.877,44.143 69.323,42.697 69.323,40.9 73.46,36.763 82.255,36.763 83.594,38.103 ; v1(80.035,44.983) 80.329,44.69 80.329,41.083 80.861,40.551 R17.1@81.661,40.551 83.056,40.551 83.594,40.013 83.594,38.103 ; J15.6@92.25,42.114 92.25,39.764 89.5,37.014 84.629,37.014 84.629,37.068 83.594,38.103
  Bottom Layer w0.3: v1(80.035,44.983) 80.353,44.666 IC1.199@80.353,43.407
LCD_VSYNC: IC1.11 J2.33 | length 47.6
  Top Layer w0.3: v1(49.661,53.213) 50.067,52.807 J2.33@50.067,51.529 ; v1(54.127,53.213) 58.461,48.88 58.461,47.978 58.725,47.713 59.96,47.713 62.481,45.192 63.893,45.192 64.492,44.593 68.082,44.593 70.129,42.545 70.129,40.894 73.702,37.321 81.102,37.321 v1(81.207,37.426)
  Bottom Layer w0.3: v1(49.661,53.213) v1(54.127,53.213) ; v1(81.207,37.426) 81.519,37.113 83.313,37.113 84.008,36.419 IC1.11@86.841,36.419
NetB1_4: B1.4 U1.12 | length 15.3
  Bottom Layer w0.3: B1.4@11.791,24.699 15.57,24.699 16.038,24.232 23.165,24.232 23.774,23.622 23.774,22.606 23.52,22.352 U1.12@22.065,22.352
NetB1_6: B1.6 U1.13 | length 10.6
  Bottom Layer w0.3: B1.6@11.791,22.799 15.806,22.799 16.629,23.622 U1.13@22.065,23.622
NetC6_1: C6.1 IC1.148 | length 5
  Bottom Layer w0.3: C6.1@53.275,36.83 53.275,37.643 56.113,37.643 56.337,37.419 IC1.148@57.365,37.419
NetC7_1: C7.1 IC1.92 | length 11.3
  Top Layer w0.3: v1(67.437,16.383) 67.056,16.002 67.056,14.097 67.691,13.462 67.691,12.78 v1(68.224,12.247)
  Bottom Layer w0.2: IC1.92@65.353,13.335 IC1.92@65.353,13.931 65.353,16.461
  Bottom Layer w0.3: 65.353,16.461 65.529,16.637 67.111,16.637 67.365,16.383 v1(67.437,16.383) ; C7.1@67.818,11.241 67.818,11.841 v1(68.224,12.247)
NetC22_2: C22.2 IC1.9 Y1.1 | length 8.4
  Bottom Layer w0.3: IC1.9@86.841,37.419 89.059,37.419 90.83,39.19 90.903,39.19 ; C22.2@89.281,40.605 89.281,40.157 89.309,40.129 89.964,40.129 90.903,39.19 ; Y1.1@92.042,39.19 90.903,39.19
NetC23_2: C23.2 IC1.10 Y1.2 | length 8.5
  Bottom Layer w0.3: IC1.10@86.841,36.919 89.306,36.919 89.535,36.69 Y1.2@92.042,36.69 92.042,35.976 92.304,35.714 92.54,35.714 93.22,35.034 C23.2@93.22,34.13
NetC31_2: C31.2 IC6.5 | length 2.8
  Bottom Layer w0.3: IC6.5@28.014,55.085 30.353,55.085 C31.2@30.353,55.591
NetC40_2: C40.2 IC8.2 VR1.S1 | length 28.4
  Top Layer w0.3: v1(109.245,22.225) 109.245,23.52 VR1.S1@124.808,39.083
  Bottom Layer w0.3: IC8.2@109.243,21.09 109.243,22.223 v1(109.245,22.225) ; C40.2@124.278,42.799 124.278,41.195 124.808,40.665 VR1.S1@124.808,39.083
